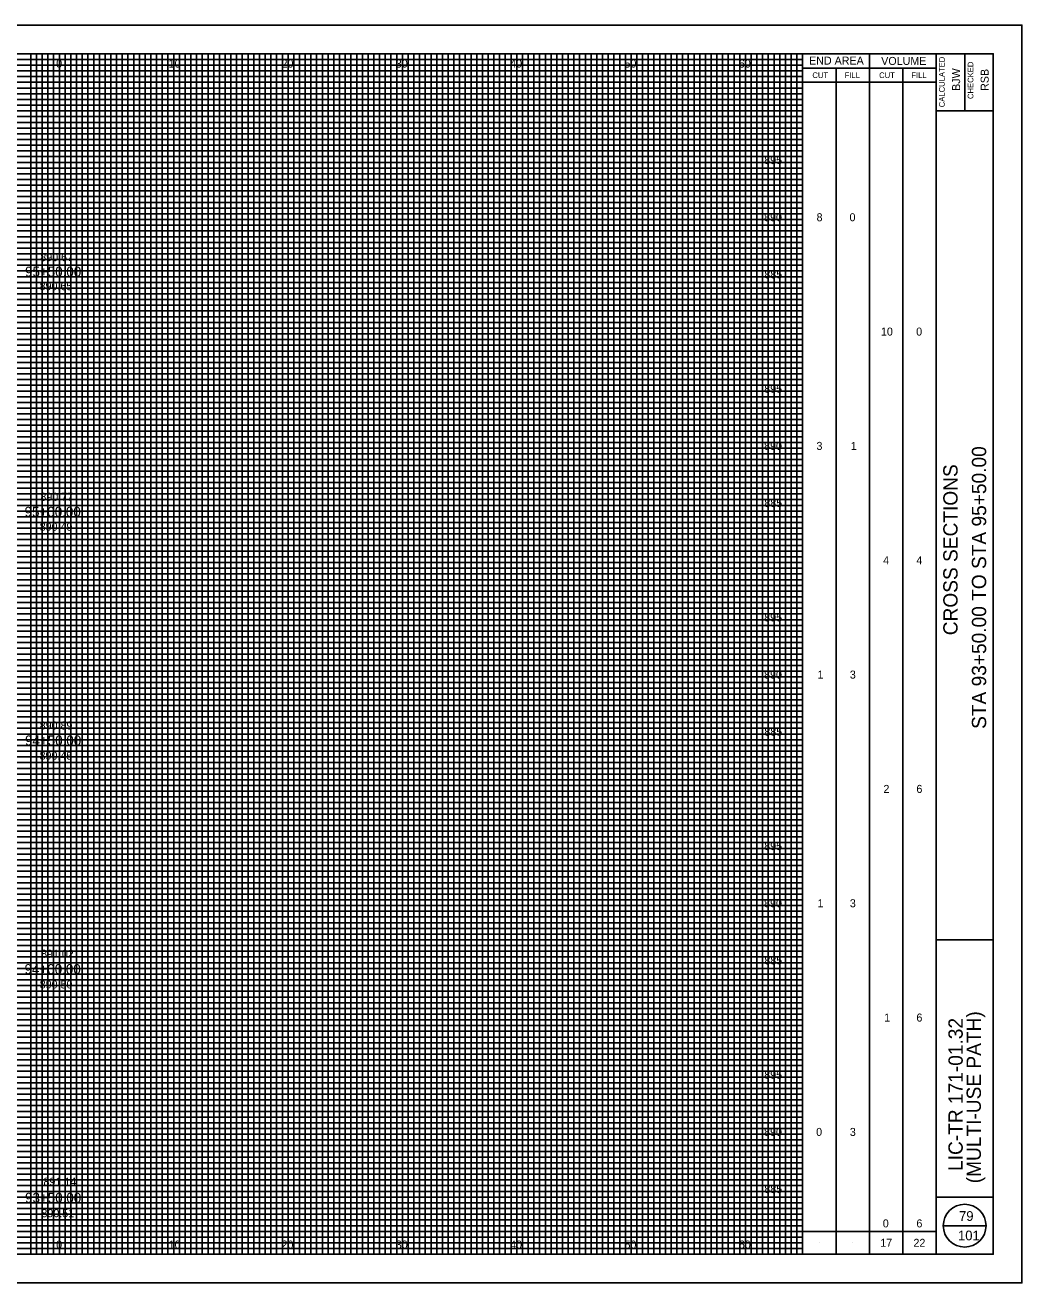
# Model space of a CAD drawing. Extents: x -10 to 160, y -2 to 3672.
# Drawn here: x 72.8 to 160, y 1147.5 to 1257.5 of the extents above; entities that cross this region are included whole.
import ezdxf

# ---------------------------------------------------------------- set-up
doc = ezdxf.new("R2010")
doc.units = 0
for name, color, linetype in [('SH_Border', 7, 'Continuous'), ('SH_Cut_Line', 7, 'Continuous'), ('SH_Data', 7, 'Continuous'), ('SH_Major_Grid_Line', 7, 'Continuous'), ('SH_Minor_Grid_Line', 7, 'Continuous'), ('SH_Text', 7, 'Continuous'), ('TX_P_10', 7, 'Continuous'), ('TX_X_10', 7, 'Continuous')]:
    doc.layers.add(name, color=color, linetype=linetype)

msp = doc.modelspace()

# ---------------------------------------------------------------- linework, layer by layer
at = {"layer": 'SH_Border'}
for p, q in [((152.5, 1150), (152.5, 1255)), ((155, 1255), (155, 1250)), ((152.5, 1250), (157.5, 1250)), ((152.5, 1177.5), (157.5, 1177.5)), ((152.5, 1155), (157.5, 1155))]:
    msp.add_line(p, q, dxfattribs=at)
msp.add_lwpolyline([(0, 1255), (157.5, 1255), (157.5, 1150), (0, 1150)], close=True, dxfattribs=at)
at = {"layer": 'SH_Cut_Line'}
msp.add_lwpolyline([(-10, 1147.5), (160, 1147.5), (160, 1257.5), (-10, 1257.5)], close=True, dxfattribs=at)
at = {"layer": 'SH_Data'}
for p, q in [((140.83, 1150), (140.83, 1255)), ((146.67, 1150), (146.67, 1255)), ((140.83, 1253.75), (152.5, 1253.75)), ((143.75, 1150), (143.75, 1253.75)), ((149.58, 1150), (149.58, 1253.75)), ((140.83, 1252.5), (152.5, 1252.5)), ((140.83, 1152), (152.5, 1152)), ((153.12, 1152.5), (156.88, 1152.5)), ((142.29, 1151), (142.29, 1151)), ((145.21, 1151), (145.21, 1151)), ((148.12, 1151), (148.12, 1151)), ((151.04, 1151), (151.04, 1151))]:
    msp.add_line(p, q, dxfattribs=at)
msp.add_circle((155, 1152.5), 1.87, dxfattribs=at)
at = {"layer": 'SH_Major_Grid_Line'}
for p, q in [((75.83, 1150), (75.83, 1255)), ((80.83, 1150), (80.83, 1255)), ((85.83, 1150), (85.83, 1255)), ((90.83, 1150), (90.83, 1255)), ((95.83, 1150), (95.83, 1255)), ((100.83, 1150), (100.83, 1255)), ((105.83, 1150), (105.83, 1255)), ((110.83, 1150), (110.83, 1255)), ((115.83, 1150), (115.83, 1255)), ((120.83, 1150), (120.83, 1255)), ((125.83, 1150), (125.83, 1255)), ((130.83, 1150), (130.83, 1255)), ((135.83, 1150), (135.83, 1255)), ((5.83, 1250), (140.83, 1250)), ((5.83, 1245), (140.83, 1245)), ((5.83, 1240), (140.83, 1240)), ((5.83, 1235), (140.83, 1235)), ((5.83, 1230), (140.83, 1230)), ((5.83, 1225), (140.83, 1225)), ((5.83, 1220), (140.83, 1220)), ((5.83, 1215), (140.83, 1215)), ((5.83, 1210), (140.83, 1210)), ((5.83, 1205), (140.83, 1205)), ((5.83, 1200), (140.83, 1200)), ((5.83, 1195), (140.83, 1195)), ((5.83, 1190), (140.83, 1190)), ((5.83, 1185), (140.83, 1185)), ((5.83, 1180), (140.83, 1180)), ((5.83, 1175), (140.83, 1175)), ((5.83, 1170), (140.83, 1170)), ((5.83, 1165), (140.83, 1165)), ((5.83, 1160), (140.83, 1160)), ((5.83, 1155), (140.83, 1155))]:
    msp.add_line(p, q, dxfattribs=at)
at = {"layer": 'SH_Minor_Grid_Line'}
for p, q in [((5.83, 1254.5), (140.83, 1254.5)), ((5.83, 1254), (140.83, 1254)), ((73.33, 1150), (73.33, 1255)), ((73.83, 1150), (73.83, 1255)), ((74.33, 1150), (74.33, 1255)), ((74.83, 1150), (74.83, 1255)), ((75.33, 1150), (75.33, 1255)), ((76.33, 1150), (76.33, 1255)), ((76.83, 1150), (76.83, 1255)), ((77.33, 1150), (77.33, 1255)), ((77.83, 1150), (77.83, 1255)), ((78.33, 1150), (78.33, 1255)), ((78.83, 1150), (78.83, 1255)), ((79.33, 1150), (79.33, 1255)), ((79.83, 1150), (79.83, 1255)), ((80.33, 1150), (80.33, 1255)), ((81.33, 1150), (81.33, 1255)), ((81.83, 1150), (81.83, 1255)), ((82.33, 1150), (82.33, 1255)), ((82.83, 1150), (82.83, 1255)), ((83.33, 1150), (83.33, 1255)), ((83.83, 1150), (83.83, 1255)), ((84.33, 1150), (84.33, 1255)), ((84.83, 1150), (84.83, 1255)), ((85.33, 1150), (85.33, 1255)), ((86.33, 1150), (86.33, 1255)), ((86.83, 1150), (86.83, 1255)), ((87.33, 1150), (87.33, 1255)), ((87.83, 1150), (87.83, 1255)), ((88.33, 1150), (88.33, 1255)), ((88.83, 1150), (88.83, 1255)), ((89.33, 1150), (89.33, 1255)), ((89.83, 1150), (89.83, 1255)), ((90.33, 1150), (90.33, 1255)), ((91.33, 1150), (91.33, 1255)), ((91.83, 1150), (91.83, 1255)), ((92.33, 1150), (92.33, 1255)), ((92.83, 1150), (92.83, 1255)), ((93.33, 1150), (93.33, 1255)), ((93.83, 1150), (93.83, 1255)), ((94.33, 1150), (94.33, 1255)), ((94.83, 1150), (94.83, 1255)), ((95.33, 1150), (95.33, 1255)), ((96.33, 1150), (96.33, 1255)), ((96.83, 1150), (96.83, 1255)), ((97.33, 1150), (97.33, 1255)), ((97.83, 1150), (97.83, 1255)), ((98.33, 1150), (98.33, 1255)), ((98.83, 1150), (98.83, 1255)), ((99.33, 1150), (99.33, 1255)), ((99.83, 1150), (99.83, 1255)), ((100.33, 1150), (100.33, 1255)), ((101.33, 1150), (101.33, 1255)), ((101.83, 1150), (101.83, 1255)), ((102.33, 1150), (102.33, 1255)), ((102.83, 1150), (102.83, 1255)), ((103.33, 1150), (103.33, 1255)), ((103.83, 1150), (103.83, 1255)), ((104.33, 1150), (104.33, 1255)), ((104.83, 1150), (104.83, 1255)), ((105.33, 1150), (105.33, 1255)), ((106.33, 1150), (106.33, 1255)), ((106.83, 1150), (106.83, 1255)), ((107.33, 1150), (107.33, 1255)), ((107.83, 1150), (107.83, 1255)), ((108.33, 1150), (108.33, 1255)), ((108.83, 1150), (108.83, 1255)), ((109.33, 1150), (109.33, 1255)), ((109.83, 1150), (109.83, 1255)), ((110.33, 1150), (110.33, 1255)), ((111.33, 1150), (111.33, 1255)), ((111.83, 1150), (111.83, 1255)), ((112.33, 1150), (112.33, 1255)), ((112.83, 1150), (112.83, 1255)), ((113.33, 1150), (113.33, 1255)), ((113.83, 1150), (113.83, 1255)), ((114.33, 1150), (114.33, 1255)), ((114.83, 1150), (114.83, 1255)), ((115.33, 1150), (115.33, 1255)), ((116.33, 1150), (116.33, 1255)), ((116.83, 1150), (116.83, 1255)), ((117.33, 1150), (117.33, 1255)), ((117.83, 1150), (117.83, 1255)), ((118.33, 1150), (118.33, 1255)), ((118.83, 1150), (118.83, 1255)), ((119.33, 1150), (119.33, 1255)), ((119.83, 1150), (119.83, 1255)), ((120.33, 1150), (120.33, 1255)), ((121.33, 1150), (121.33, 1255)), ((121.83, 1150), (121.83, 1255)), ((122.33, 1150), (122.33, 1255)), ((122.83, 1150), (122.83, 1255)), ((123.33, 1150), (123.33, 1255)), ((123.83, 1150), (123.83, 1255)), ((124.33, 1150), (124.33, 1255)), ((124.83, 1150), (124.83, 1255)), ((125.33, 1150), (125.33, 1255)), ((126.33, 1150), (126.33, 1255)), ((126.83, 1150), (126.83, 1255)), ((127.33, 1150), (127.33, 1255)), ((127.83, 1150), (127.83, 1255)), ((128.33, 1150), (128.33, 1255)), ((128.83, 1150), (128.83, 1255)), ((129.33, 1150), (129.33, 1255)), ((129.83, 1150), (129.83, 1255)), ((130.33, 1150), (130.33, 1255)), ((131.33, 1150), (131.33, 1255)), ((131.83, 1150), (131.83, 1255)), ((132.33, 1150), (132.33, 1255)), ((132.83, 1150), (132.83, 1255)), ((133.33, 1150), (133.33, 1255)), ((133.83, 1150), (133.83, 1255)), ((134.33, 1150), (134.33, 1255)), ((134.83, 1150), (134.83, 1255)), ((135.33, 1150), (135.33, 1255)), ((136.33, 1150), (136.33, 1255)), ((136.83, 1150), (136.83, 1255)), ((137.33, 1150), (137.33, 1255)), ((137.83, 1150), (137.83, 1255)), ((138.33, 1150), (138.33, 1255)), ((138.83, 1150), (138.83, 1255)), ((139.33, 1150), (139.33, 1255)), ((139.83, 1150), (139.83, 1255)), ((140.33, 1150), (140.33, 1255)), ((5.83, 1253.5), (140.83, 1253.5)), ((5.83, 1253), (140.83, 1253)), ((5.83, 1252.5), (140.83, 1252.5)), ((5.83, 1252), (140.83, 1252)), ((5.83, 1251.5), (140.83, 1251.5)), ((5.83, 1251), (140.83, 1251)), ((5.83, 1250.5), (140.83, 1250.5)), ((5.83, 1249.5), (140.83, 1249.5)), ((5.83, 1249), (140.83, 1249)), ((5.83, 1248.5), (140.83, 1248.5)), ((5.83, 1248), (140.83, 1248)), ((5.83, 1247.5), (140.83, 1247.5)), ((5.83, 1247), (140.83, 1247)), ((5.83, 1246.5), (140.83, 1246.5)), ((5.83, 1246), (140.83, 1246)), ((5.83, 1245.5), (140.83, 1245.5)), ((5.83, 1244.5), (140.83, 1244.5)), ((5.83, 1244), (140.83, 1244)), ((5.83, 1243.5), (140.83, 1243.5)), ((5.83, 1243), (140.83, 1243)), ((5.83, 1242.5), (140.83, 1242.5)), ((5.83, 1242), (140.83, 1242)), ((5.83, 1241.5), (140.83, 1241.5)), ((5.83, 1241), (140.83, 1241)), ((5.83, 1240.5), (140.83, 1240.5)), ((5.83, 1239.5), (140.83, 1239.5)), ((5.83, 1239), (140.83, 1239)), ((5.83, 1238.5), (140.83, 1238.5)), ((5.83, 1238), (140.83, 1238)), ((5.83, 1237.5), (140.83, 1237.5)), ((5.83, 1237), (140.83, 1237)), ((5.83, 1236.5), (140.83, 1236.5)), ((5.83, 1236), (140.83, 1236)), ((5.83, 1235.5), (140.83, 1235.5)), ((5.83, 1234.5), (140.83, 1234.5)), ((5.83, 1234), (140.83, 1234)), ((5.83, 1233.5), (140.83, 1233.5)), ((5.83, 1233), (140.83, 1233)), ((5.83, 1232.5), (140.83, 1232.5)), ((5.83, 1232), (140.83, 1232)), ((5.83, 1231.5), (140.83, 1231.5)), ((5.83, 1231), (140.83, 1231)), ((5.83, 1230.5), (140.83, 1230.5)), ((5.83, 1229.5), (140.83, 1229.5)), ((5.83, 1229), (140.83, 1229)), ((5.83, 1228.5), (140.83, 1228.5)), ((5.83, 1228), (140.83, 1228)), ((5.83, 1227.5), (140.83, 1227.5)), ((5.83, 1227), (140.83, 1227)), ((5.83, 1226.5), (140.83, 1226.5)), ((5.83, 1226), (140.83, 1226)), ((5.83, 1225.5), (140.83, 1225.5)), ((5.83, 1224.5), (140.83, 1224.5)), ((5.83, 1224), (140.83, 1224)), ((5.83, 1223.5), (140.83, 1223.5)), ((5.83, 1223), (140.83, 1223)), ((5.83, 1222.5), (140.83, 1222.5)), ((5.83, 1222), (140.83, 1222)), ((5.83, 1221.5), (140.83, 1221.5)), ((5.83, 1221), (140.83, 1221)), ((5.83, 1220.5), (140.83, 1220.5)), ((5.83, 1219.5), (140.83, 1219.5)), ((5.83, 1219), (140.83, 1219)), ((5.83, 1218.5), (140.83, 1218.5)), ((5.83, 1218), (140.83, 1218)), ((5.83, 1217.5), (140.83, 1217.5)), ((5.83, 1217), (140.83, 1217)), ((5.83, 1216.5), (140.83, 1216.5)), ((5.83, 1216), (140.83, 1216)), ((5.83, 1215.5), (140.83, 1215.5)), ((5.83, 1214.5), (140.83, 1214.5)), ((5.83, 1214), (140.83, 1214)), ((5.83, 1213.5), (140.83, 1213.5)), ((5.83, 1213), (140.83, 1213)), ((5.83, 1212.5), (140.83, 1212.5)), ((5.83, 1212), (140.83, 1212)), ((5.83, 1211.5), (140.83, 1211.5)), ((5.83, 1211), (140.83, 1211)), ((5.83, 1210.5), (140.83, 1210.5)), ((5.83, 1209.5), (140.83, 1209.5)), ((5.83, 1209), (140.83, 1209)), ((5.83, 1208.5), (140.83, 1208.5)), ((5.83, 1208), (140.83, 1208)), ((5.83, 1207.5), (140.83, 1207.5)), ((5.83, 1207), (140.83, 1207)), ((5.83, 1206.5), (140.83, 1206.5)), ((5.83, 1206), (140.83, 1206)), ((5.83, 1205.5), (140.83, 1205.5)), ((5.83, 1204.5), (140.83, 1204.5)), ((5.83, 1204), (140.83, 1204)), ((5.83, 1203.5), (140.83, 1203.5)), ((5.83, 1203), (140.83, 1203)), ((5.83, 1202.5), (140.83, 1202.5)), ((5.83, 1202), (140.83, 1202)), ((5.83, 1201.5), (140.83, 1201.5)), ((5.83, 1201), (140.83, 1201)), ((5.83, 1200.5), (140.83, 1200.5)), ((5.83, 1199.5), (140.83, 1199.5)), ((5.83, 1199), (140.83, 1199)), ((5.83, 1198.5), (140.83, 1198.5)), ((5.83, 1198), (140.83, 1198)), ((5.83, 1197.5), (140.83, 1197.5)), ((5.83, 1197), (140.83, 1197)), ((5.83, 1196.5), (140.83, 1196.5)), ((5.83, 1196), (140.83, 1196)), ((5.83, 1195.5), (140.83, 1195.5)), ((5.83, 1194.5), (140.83, 1194.5)), ((5.83, 1194), (140.83, 1194)), ((5.83, 1193.5), (140.83, 1193.5)), ((5.83, 1193), (140.83, 1193)), ((5.83, 1192.5), (140.83, 1192.5)), ((5.83, 1192), (140.83, 1192)), ((5.83, 1191.5), (140.83, 1191.5)), ((5.83, 1191), (140.83, 1191)), ((5.83, 1190.5), (140.83, 1190.5)), ((5.83, 1189.5), (140.83, 1189.5)), ((5.83, 1189), (140.83, 1189)), ((5.83, 1188.5), (140.83, 1188.5)), ((5.83, 1188), (140.83, 1188)), ((5.83, 1187.5), (140.83, 1187.5)), ((5.83, 1187), (140.83, 1187)), ((5.83, 1186.5), (140.83, 1186.5)), ((5.83, 1186), (140.83, 1186)), ((5.83, 1185.5), (140.83, 1185.5)), ((5.83, 1184.5), (140.83, 1184.5)), ((5.83, 1184), (140.83, 1184)), ((5.83, 1183.5), (140.83, 1183.5)), ((5.83, 1183), (140.83, 1183)), ((5.83, 1182.5), (140.83, 1182.5)), ((5.83, 1182), (140.83, 1182)), ((5.83, 1181.5), (140.83, 1181.5)), ((5.83, 1181), (140.83, 1181)), ((5.83, 1180.5), (140.83, 1180.5)), ((5.83, 1179.5), (140.83, 1179.5)), ((5.83, 1179), (140.83, 1179)), ((5.83, 1178.5), (140.83, 1178.5)), ((5.83, 1178), (140.83, 1178)), ((5.83, 1177.5), (140.83, 1177.5)), ((5.83, 1177), (140.83, 1177)), ((5.83, 1176.5), (140.83, 1176.5)), ((5.83, 1176), (140.83, 1176)), ((5.83, 1175.5), (140.83, 1175.5)), ((5.83, 1174.5), (140.83, 1174.5)), ((5.83, 1174), (140.83, 1174)), ((5.83, 1173.5), (140.83, 1173.5)), ((5.83, 1173), (140.83, 1173)), ((5.83, 1172.5), (140.83, 1172.5)), ((5.83, 1172), (140.83, 1172)), ((5.83, 1171.5), (140.83, 1171.5)), ((5.83, 1171), (140.83, 1171)), ((5.83, 1170.5), (140.83, 1170.5)), ((5.83, 1169.5), (140.83, 1169.5)), ((5.83, 1169), (140.83, 1169)), ((5.83, 1168.5), (140.83, 1168.5)), ((5.83, 1168), (140.83, 1168)), ((5.83, 1167.5), (140.83, 1167.5)), ((5.83, 1167), (140.83, 1167)), ((5.83, 1166.5), (140.83, 1166.5)), ((5.83, 1166), (140.83, 1166)), ((5.83, 1165.5), (140.83, 1165.5)), ((5.83, 1164.5), (140.83, 1164.5)), ((5.83, 1164), (140.83, 1164)), ((5.83, 1163.5), (140.83, 1163.5)), ((5.83, 1163), (140.83, 1163)), ((5.83, 1162.5), (140.83, 1162.5)), ((5.83, 1162), (140.83, 1162)), ((5.83, 1161.5), (140.83, 1161.5)), ((5.83, 1161), (140.83, 1161)), ((5.83, 1160.5), (140.83, 1160.5)), ((5.83, 1159.5), (140.83, 1159.5)), ((5.83, 1159), (140.83, 1159)), ((5.83, 1158.5), (140.83, 1158.5)), ((5.83, 1158), (140.83, 1158)), ((5.83, 1157.5), (140.83, 1157.5)), ((5.83, 1157), (140.83, 1157)), ((5.83, 1156.5), (140.83, 1156.5)), ((5.83, 1156), (140.83, 1156)), ((5.83, 1155.5), (140.83, 1155.5)), ((5.83, 1154.5), (140.83, 1154.5)), ((5.83, 1154), (140.83, 1154)), ((5.83, 1153.5), (140.83, 1153.5)), ((5.83, 1153), (140.83, 1153)), ((5.83, 1152.5), (140.83, 1152.5)), ((5.83, 1152), (140.83, 1152)), ((5.83, 1151.5), (140.83, 1151.5)), ((5.83, 1151), (140.83, 1151)), ((5.83, 1150.5), (140.83, 1150.5))]:
    msp.add_line(p, q, dxfattribs=at)

# ---------------------------------------------------------------- texts
at = {"layer": 'SH_Data'}
for s, height, p in [('END AREA', 0.7, (141.39, 1254.05)), ('VOLUME', 0.7, (147.7, 1254.02)), ('CUT', 0.5, (141.68, 1252.87)), ('FILL', 0.5, (144.5, 1252.87)), ('CUT', 0.5, (147.52, 1252.87)), ('FILL', 0.5, (150.34, 1252.87)), ('79', 0.85, (154.51, 1152.92)), ('101', 0.85, (154.42, 1151.22))]:
    msp.add_text(s, height=height, dxfattribs=at).set_placement(p)
for s, height, p in [('CALCULATED', 0.5, (153.26, 1250.32)), ('CHECKED', 0.5, (155.76, 1251.04)), ('BJW', 0.7, (154.6, 1251.75)), ('RSB', 0.7, (157.1, 1251.75)), ('STA 93+50.00 TO STA 95+50.00', 1.25, (156.88, 1195.95)), ('CROSS SECTIONS', 1.25, (154.38, 1204.14)), ('LIC-TR 171-01.32', 1.25, (154.83, 1157.29)), ('(MULTI-USE PATH)', 1.25, (156.42, 1156.21))]:
    msp.add_text(s, height=height, rotation=90, dxfattribs=at).set_placement(p)
at = {"layer": 'SH_Text'}
for s, height, p in [('0', 0.7, (75.55, 1253.79)), ('10', 0.7, (85.39, 1253.79)), ('20', 0.7, (95.26, 1253.79)), ('30', 0.7, (105.25, 1253.79)), ('40', 0.7, (115.25, 1253.79)), ('50', 0.7, (125.25, 1253.79)), ('60', 0.7, (135.25, 1253.79)), ('895', 0.7, (137.47, 1245.35)), ('890', 0.7, (137.46, 1240.35)), ('8', 0.7, (142.05, 1240.35)), ('0', 0.7, (144.93, 1240.35)), ('95+50.00', 0.875, (72.83, 1235.5)), ('885', 0.7, (137.48, 1235.35)), ('10', 0.7, (147.68, 1230.35)), ('0', 0.7, (150.76, 1230.35)), ('895', 0.7, (137.47, 1225.35)), ('890', 0.7, (137.46, 1220.35)), ('3', 0.7, (142.04, 1220.35)), ('1', 0.7, (145.04, 1220.35)), ('885', 0.7, (137.48, 1215.35)), ('95+00.00', 0.875, (72.79, 1214.5)), ('4', 0.7, (147.87, 1210.35)), ('4', 0.7, (150.78, 1210.35)), ('895', 0.7, (137.47, 1205.35)), ('890', 0.7, (137.46, 1200.35)), ('1', 0.7, (142.13, 1200.35)), ('3', 0.7, (144.96, 1200.35)), ('885', 0.7, (137.48, 1195.35)), ('94+50.00', 0.875, (72.83, 1194.5)), ('2', 0.7, (147.9, 1190.35)), ('6', 0.7, (150.78, 1190.35)), ('895', 0.7, (137.47, 1185.35)), ('890', 0.7, (137.46, 1180.35)), ('1', 0.7, (142.13, 1180.35)), ('3', 0.7, (144.96, 1180.35)), ('885', 0.7, (137.48, 1175.35)), ('94+00.00', 0.875, (72.79, 1174.5)), ('1', 0.7, (147.96, 1170.35)), ('6', 0.7, (150.78, 1170.35)), ('895', 0.7, (137.47, 1165.35)), ('890', 0.7, (137.46, 1160.35)), ('0', 0.7, (142.01, 1160.35)), ('3', 0.7, (144.96, 1160.35)), ('93+50.00', 0.875, (72.83, 1154.5)), ('885', 0.7, (137.48, 1155.35)), ('0', 0.7, (147.84, 1152.35)), ('6', 0.7, (150.78, 1152.35)), ('0', 0.7, (75.55, 1150.5)), ('10', 0.7, (85.39, 1150.5)), ('20', 0.7, (95.26, 1150.5)), ('30', 0.7, (105.25, 1150.5)), ('40', 0.7, (115.25, 1150.5)), ('50', 0.7, (125.25, 1150.5)), ('60', 0.7, (135.25, 1150.5)), ('17', 0.7, (147.62, 1150.65)), ('22', 0.7, (150.52, 1150.65))]:
    msp.add_text(s, height=height, dxfattribs=at).set_placement(p)
at = {"layer": 'TX_P_10'}
for s, p in [('890.67', (74.16, 1236.86)), ('890.77', (74.17, 1215.9)), ('890.89', (74.11, 1195.9)), ('891.02', (74.23, 1175.93)), ('891.14', (74.44, 1156))]:
    msp.add_text(s, height=0.7, dxfattribs=at).set_placement(p)
at = {"layer": 'TX_X_10'}
for s, p in [('890.65', (74.1, 1234.32)), ('890.49', (74.11, 1213.28)), ('890.45', (74.1, 1193.26)), ('890.50', (74.11, 1173.25)), ('890.51', (74.26, 1153.24))]:
    msp.add_text(s, height=0.7, dxfattribs=at).set_placement(p)

doc.saveas('drawing.dxf')
